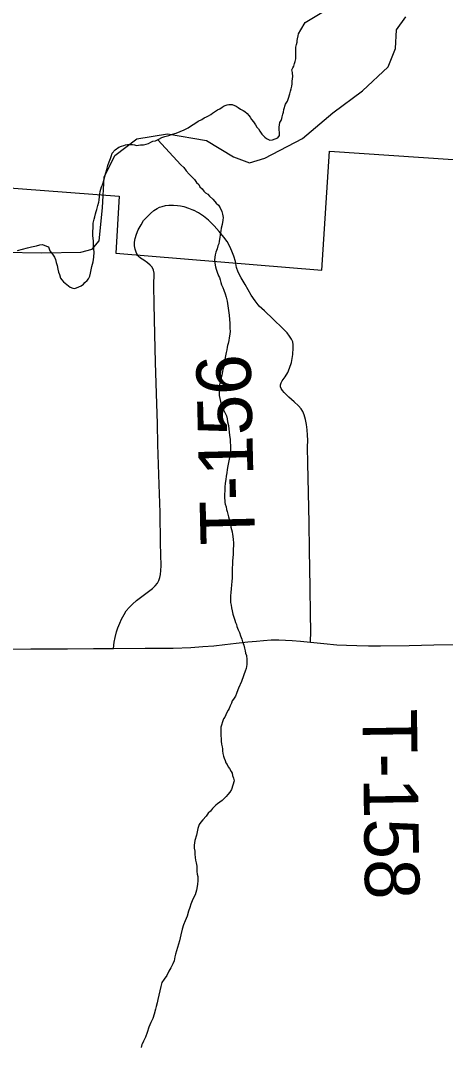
# Model space of a CAD drawing. Extents: x -11.4 to 84.1, y 11.1 to 59.
# Drawn here: x 29.384 to 29.827, y 45.561 to 46.631 of the extents above; entities that cross this region are included whole.
import ezdxf

# ---------------------------------------------------------------- set-up
doc = ezdxf.new("R2010")
doc.units = 0
for name, color, linetype in [('GM_X_Corporation', 7, 'Continuous'), ('GM_X_County_Road', 7, 'Continuous'), ('GM_X_Major_River', 7, 'Continuous'), ('GM_X_Minor_River', 7, 'Continuous'), ('GM_X_Rail_Line', 7, 'Continuous'), ('GM_X_Township_Road', 7, 'Continuous'), ('GM_X_Township_Road_Text', 7, 'Continuous')]:
    doc.layers.add(name, color=color, linetype=linetype)

msp = doc.modelspace()

# ---------------------------------------------------------------- linework, layer by layer
at = {"layer": 'GM_X_Corporation'}
msp.add_lwpolyline([(29.2807, 46.4633), (29.4869, 46.4478), (29.4834, 46.3883), (29.6985, 46.3706), (29.7063, 46.4947), (29.8352, 46.4859), (29.9622, 46.4788), (29.9464, 46.816), (29.9432, 46.8688), (29.9372, 46.8931), (29.8985, 46.896), (29.9001, 46.9199), (29.5467, 46.9424), (29.5434, 46.8903), (29.5061, 46.8927), (29.5056, 46.8842), (29.4682, 46.8866), (29.4704, 46.9206), (29.4238, 46.9236), (29.4228, 46.908), (29.2952, 46.9163)], dxfattribs=at)
at = {"layer": 'GM_X_County_Road'}
msp.add_lwpolyline([(29.345, 45.9758), (29.3948, 45.9761), (29.433, 45.9762), (29.4602, 45.9764), (29.4812, 45.9765), (29.5143, 45.9768), (29.5433, 45.977), (29.5619, 45.9777), (29.5743, 45.9785), (29.5859, 45.9794), (29.5972, 45.9807), (29.6091, 45.9821), (29.6211, 45.9835), (29.6303, 45.9843), (29.6377, 45.985), (29.6455, 45.9854), (29.6534, 45.9855), (29.6605, 45.9852), (29.6675, 45.9848), (29.676, 45.9841), (29.6866, 45.9831), (29.7003, 45.9817), (29.714, 45.9805), (29.7242, 45.9799), (29.7348, 45.9795), (29.747, 45.9793), (29.7594, 45.9794), (29.7894, 45.9798), (29.8151, 45.9802), (29.8386, 45.9808)], dxfattribs=at)
at = {"layer": 'GM_X_Major_River'}
for points in [[(29.6811, 46.6285), (29.702, 46.641)], [(29.6664, 46.5595), (29.6671, 46.5621), (29.6675, 46.5648), (29.6674, 46.5671), (29.6678, 46.5701), (29.6681, 46.572), (29.6677, 46.5766), (29.6672, 46.5792), (29.6683, 46.5812), (29.6691, 46.5831), (29.6698, 46.5858), (29.6705, 46.588), (29.6712, 46.5907), (29.6711, 46.5964), (29.6714, 46.5995), (29.6714, 46.6029), (29.6721, 46.6056), (29.6728, 46.6079), (29.6728, 46.6098), (29.6731, 46.6117), (29.6738, 46.6147), (29.6742, 46.6166), (29.6765, 46.621), (29.6811, 46.6285)], [(29.4617, 46.426), (29.4624, 46.4291), (29.4631, 46.4318), (29.4638, 46.4337), (29.4649, 46.4379), (29.466, 46.4413), (29.4663, 46.4436), (29.4666, 46.4474), (29.467, 46.4497), (29.4673, 46.4524), (29.468, 46.455), (29.4687, 46.4573), (29.4695, 46.4596), (29.4702, 46.4615), (29.4709, 46.4642), (29.4731, 46.4719), (29.4741, 46.4753), (29.4752, 46.4795), (29.4767, 46.4833), (29.4781, 46.4868), (29.4788, 46.4891), (29.4799, 46.4925), (29.4829, 46.496), (29.4867, 46.4987), (29.4893, 46.4999), (29.4919, 46.5003), (29.4938, 46.5011), (29.4957, 46.5015), (29.4991, 46.5016), (29.501, 46.5016), (29.5029, 46.5012), (29.5052, 46.5005), (29.5094, 46.501), (29.5124, 46.501), (29.5151, 46.5018), (29.5177, 46.5026), (29.52, 46.5038), (29.5223, 46.505), (29.5249, 46.5054), (29.5283, 46.507), (29.5317, 46.5086), (29.5347, 46.5098), (29.5389, 46.511), (29.5426, 46.5122), (29.5464, 46.5134), (29.5506, 46.515), (29.5547, 46.5169), (29.5589, 46.5189), (29.5626, 46.5212), (29.566, 46.5232), (29.5694, 46.5259), (29.5731, 46.5275), (29.5758, 46.5291), (29.578, 46.5302), (29.5803, 46.5314), (29.5826, 46.5326), (29.5844, 46.5342), (29.5897, 46.5377), (29.5919, 46.5388), (29.5946, 46.5404), (29.5965, 46.5416), (29.5995, 46.5428), (29.6014, 46.5432), (29.6048, 46.5432), (29.609, 46.5414), (29.6113, 46.5399), (29.6136, 46.5384), (29.6163, 46.537), (29.6182, 46.5358), (29.6205, 46.5336), (29.6221, 46.5317), (29.6236, 46.5299), (29.6252, 46.5276), (29.6271, 46.525), (29.6291, 46.522), (29.6306, 46.5197), (29.6322, 46.5178), (29.6337, 46.5152), (29.6357, 46.5122), (29.6388, 46.5092), (29.6407, 46.5077), (29.6442, 46.5059), (29.6468, 46.5063), (29.6525, 46.5083), (29.6543, 46.511), (29.6543, 46.514), (29.6538, 46.5167), (29.6538, 46.5197), (29.6545, 46.5243), (29.656, 46.5266), (29.6567, 46.5285), (29.657, 46.5304), (29.6577, 46.5331), (29.6585, 46.535), (29.6588, 46.538), (29.6606, 46.5434), (29.6625, 46.5465), (29.6635, 46.5499), (29.665, 46.5541), (29.6657, 46.5572), (29.6664, 46.5595)], [(29.381, 46.3912), (29.3863, 46.3925), (29.3916, 46.3937), (29.3957, 46.3949), (29.401, 46.3961), (29.4044, 46.397), (29.4071, 46.3974), (29.4113, 46.3955), (29.4132, 46.3948), (29.4148, 46.3907), (29.4175, 46.3873), (29.4195, 46.3843), (29.4206, 46.3816), (29.4214, 46.3786), (29.4223, 46.3756), (29.4231, 46.3718), (29.4239, 46.3684), (29.4247, 46.3661), (29.4259, 46.3623), (29.4274, 46.3605), (29.429, 46.3586), (29.4359, 46.353), (29.4386, 46.3519), (29.4409, 46.3515), (29.445, 46.3531), (29.4473, 46.3543), (29.4499, 46.3559), (29.4514, 46.3578), (29.4537, 46.3597), (29.4552, 46.3617), (29.4566, 46.3644), (29.4573, 46.3674), (29.458, 46.3708), (29.4587, 46.3743), (29.4598, 46.3792), (29.4605, 46.3842), (29.4608, 46.3895), (29.4603, 46.3956), (29.4602, 46.4013), (29.4597, 46.4062), (29.4596, 46.4108), (29.46, 46.4146), (29.4599, 46.4176), (29.4599, 46.4195), (29.4609, 46.4237), (29.4617, 46.426)]]:
    msp.add_lwpolyline(points, dxfattribs=at)
at = {"layer": 'GM_X_Minor_River'}
for points in [[(29.5273, 46.5065), (29.5515, 46.4804), (29.5546, 46.4774), (29.557, 46.474), (29.56, 46.4706), (29.5631, 46.4676), (29.5655, 46.465), (29.5678, 46.462), (29.5701, 46.4598), (29.5713, 46.4575), (29.5736, 46.4553), (29.5755, 46.453), (29.5771, 46.4511), (29.5794, 46.4496), (29.5813, 46.4478), (29.5848, 46.4444), (29.5867, 46.4422), (29.5883, 46.4403), (29.5906, 46.4384), (29.5925, 46.4354), (29.5941, 46.4316), (29.5949, 46.429), (29.5954, 46.4256), (29.595, 46.4225), (29.5943, 46.4183), (29.5933, 46.4145), (29.5929, 46.4115), (29.5926, 46.4096), (29.5923, 46.4069), (29.5919, 46.405), (29.5916, 46.4027), (29.5912, 46.4008), (29.5909, 46.3981), (29.5898, 46.3958), (29.5891, 46.3928), (29.588, 46.3893), (29.5873, 46.3867), (29.5866, 46.3813), (29.5867, 46.3779), (29.5875, 46.3741), (29.5883, 46.3715), (29.5891, 46.3684), (29.5907, 46.3647), (29.5915, 46.3628), (29.5923, 46.3605), (29.5931, 46.3579), (29.5939, 46.3552), (29.5951, 46.3526), (29.5963, 46.3499), (29.5975, 46.3461), (29.5987, 46.3424), (29.5995, 46.3382), (29.6003, 46.3336), (29.6012, 46.3287), (29.6016, 46.3238), (29.6021, 46.3192), (29.6025, 46.3154), (29.6026, 46.3124), (29.6026, 46.3097), (29.6027, 46.3071), (29.6023, 46.304), (29.6016, 46.3002), (29.6013, 46.2975), (29.6006, 46.2941), (29.5999, 46.2922), (29.5995, 46.2903), (29.5992, 46.2876), (29.5985, 46.2849), (29.5978, 46.2815), (29.5971, 46.2777), (29.5964, 46.2742), (29.5961, 46.2704), (29.595, 46.267), (29.5943, 46.2628), (29.5936, 46.2598), (29.5929, 46.2575), (29.5925, 46.2544), (29.5918, 46.251), (29.5919, 46.2479), (29.5912, 46.2453), (29.5912, 46.2426), (29.5913, 46.2399), (29.5933, 46.2308), (29.5941, 46.2278), (29.5957, 46.2252), (29.5969, 46.2229), (29.598, 46.221), (29.5988, 46.2188), (29.5996, 46.2157), (29.6001, 46.2127), (29.6009, 46.2089), (29.6013, 46.2051), (29.6018, 46.2021), (29.6022, 46.1983), (29.6027, 46.1945), (29.6027, 46.1911), (29.6031, 46.1884), (29.6032, 46.1854), (29.6032, 46.1827), (29.6033, 46.1797), (29.6026, 46.177)], [(29.6026, 46.177), (29.6019, 46.1739), (29.6012, 46.1701), (29.6005, 46.1667), (29.5998, 46.1629), (29.5994, 46.1595), (29.5987, 46.156), (29.5984, 46.1526), (29.5977, 46.1488), (29.5974, 46.1446), (29.5971, 46.1404), (29.5968, 46.1377), (29.5968, 46.1355), (29.5969, 46.1328), (29.5973, 46.1309), (29.5973, 46.1286), (29.5977, 46.1267), (29.5985, 46.1241), (29.5989, 46.1214), (29.5997, 46.1192), (29.6002, 46.1165), (29.601, 46.1135), (29.6022, 46.1097), (29.603, 46.1063), (29.6034, 46.1029), (29.6042, 46.1006), (29.6047, 46.0979), (29.6051, 46.0953), (29.6055, 46.0934), (29.6059, 46.0896), (29.6064, 46.0869), (29.6058, 46.077), (29.6058, 46.0744), (29.6055, 46.0713), (29.6052, 46.0675), (29.6052, 46.0641), (29.6049, 46.0607), (29.605, 46.0569), (29.605, 46.0535), (29.6047, 46.05), (29.6044, 46.0462), (29.6041, 46.0428), (29.6038, 46.0386), (29.6034, 46.0348), (29.6031, 46.0314), (29.6032, 46.0283), (29.6032, 46.0245), (29.6037, 46.0215), (29.6041, 46.0188), (29.6049, 46.0158), (29.6057, 46.0124), (29.6065, 46.009), (29.6077, 46.006), (29.6085, 46.0037), (29.6093, 46.0014), (29.6097, 45.9995), (29.6113, 45.9958), (29.6125, 45.9931), (29.6137, 45.9897), (29.6149, 45.9863), (29.6157, 45.9833), (29.6169, 45.9799), (29.6177, 45.9769), (29.6185, 45.9742), (29.6189, 45.9716), (29.6197, 45.9693), (29.6202, 45.9651), (29.6202, 45.9617), (29.6203, 45.9598), (29.6196, 45.9556), (29.6185, 45.9529), (29.617, 45.9491), (29.6159, 45.946), (29.6152, 45.9441), (29.6145, 45.9422), (29.6116, 45.9353), (29.6108, 45.9334), (29.6094, 45.9296), (29.6083, 45.9269), (29.6064, 45.9238), (29.6049, 45.9219), (29.6042, 45.9196), (29.6028, 45.9169), (29.6017, 45.9142), (29.6006, 45.9123), (29.5991, 45.9092), (29.5984, 45.9073), (29.5973, 45.905), (29.5958, 45.9031), (29.5947, 45.9), (29.5936, 45.8966), (29.5929, 45.8947), (29.5929, 45.8928), (29.5929, 45.8901), (29.593, 45.8878), (29.593, 45.8856), (29.5934, 45.8829), (29.5935, 45.8799), (29.5939, 45.8768), (29.5944, 45.8742), (29.5948, 45.8719)], [(29.5948, 45.8719), (29.5948, 45.87), (29.5952, 45.867), (29.596, 45.8643), (29.5965, 45.8624), (29.5976, 45.8598), (29.5984, 45.8575), (29.5996, 45.8556), (29.6008, 45.8534), (29.602, 45.8515), (29.6039, 45.8485), (29.6047, 45.8466), (29.6051, 45.8443), (29.6063, 45.8413), (29.6071, 45.8386), (29.6042, 45.8295), (29.6024, 45.8268), (29.6005, 45.8245), (29.5986, 45.8225), (29.5964, 45.8202), (29.5945, 45.8183), (29.5919, 45.8163), (29.5897, 45.8148), (29.5878, 45.8132), (29.5844, 45.8098), (29.5822, 45.8071), (29.5799, 45.8051), (29.5777, 45.802), (29.5744, 45.7982), (29.5721, 45.7955), (29.5703, 45.7932), (29.5692, 45.789), (29.5678, 45.7821), (29.566, 45.7764), (29.5653, 45.7718), (29.5654, 45.7684), (29.5658, 45.7653), (29.5658, 45.7623), (29.5663, 45.7589), (29.5667, 45.7562), (29.5675, 45.7532), (29.568, 45.7498), (29.568, 45.7471), (29.5681, 45.7441), (29.5685, 45.7414), (29.5689, 45.7391), (29.5689, 45.7365), (29.569, 45.7346), (29.5686, 45.7312), (29.5683, 45.7285), (29.5676, 45.7247), (29.5662, 45.7201), (29.5647, 45.717), (29.5632, 45.7136), (29.5618, 45.7101), (29.5607, 45.7067), (29.5592, 45.7029), (29.5578, 45.6979), (29.556, 45.6929), (29.5542, 45.6887), (29.5527, 45.6841), (29.5513, 45.6784), (29.5499, 45.6719), (29.5459, 45.6582), (29.5452, 45.6555), (29.5449, 45.6532), (29.5445, 45.6513), (29.5431, 45.6482), (29.5409, 45.644), (29.539, 45.6405), (29.5368, 45.636), (29.5338, 45.6321), (29.5316, 45.6286), (29.5306, 45.6244), (29.5295, 45.6199), (29.5284, 45.6153), (29.5274, 45.6111), (29.5267, 45.6076), (29.5256, 45.6038), (29.5249, 45.6008), (29.5234, 45.5958), (29.522, 45.5912), (29.5202, 45.587), (29.518, 45.582), (29.5162, 45.5767), (29.5144, 45.5717), (29.5125, 45.5675), (29.5111, 45.5644), (29.5107, 45.564), (29.51, 45.561)]]:
    msp.add_lwpolyline(points, dxfattribs=at)
at = {"layer": 'GM_X_Rail_Line'}
msp.add_lwpolyline([(29.3248, 46.3901), (29.4065, 46.3888), (29.447, 46.3895), (29.4589, 46.3926), (29.4663, 46.4013), (29.4695, 46.4356), (29.4713, 46.4675), (29.4826, 46.4899), (29.5056, 46.5074), (29.5376, 46.5126), (29.578, 46.5055), (29.6061, 46.4887), (29.6229, 46.4824), (29.6391, 46.4874), (29.6783, 46.5079), (29.7099, 46.5343), (29.7408, 46.5573), (29.7676, 46.5823), (29.7751, 46.6016), (29.7763, 46.6209), (29.7859, 46.6345)], dxfattribs=at)
at = {"layer": 'GM_X_Township_Road'}
for points in [[(29.4812, 45.9765), (29.4819, 45.983), (29.4828, 45.9881), (29.4844, 45.9938), (29.4858, 45.998), (29.4876, 46.0029), (29.4895, 46.007), (29.4921, 46.0119), (29.4945, 46.0156), (29.4974, 46.0193), (29.5008, 46.0227), (29.5052, 46.0266), (29.5219, 46.039), (29.5247, 46.0417), (29.5269, 46.0447), (29.5283, 46.0474), (29.5293, 46.0505), (29.53, 46.0536), (29.5306, 46.0577), (29.5307, 46.0626), (29.5303, 46.0863), (29.5297, 46.1183), (29.5287, 46.1472), (29.5281, 46.1683), (29.5273, 46.189), (29.5269, 46.2104), (29.526, 46.2423), (29.525, 46.2743), (29.5243, 46.304), (29.5235, 46.3351), (29.5232, 46.3546), (29.5234, 46.3675), (29.523, 46.3706), (29.5215, 46.3736), (29.5193, 46.3758), (29.5165, 46.3782), (29.5128, 46.3809), (29.5092, 46.3832), (29.507, 46.3853), (29.5051, 46.3883), (29.5036, 46.3924), (29.503, 46.396), (29.5031, 46.3996), (29.5037, 46.4035), (29.505, 46.408), (29.507, 46.4125), (29.5099, 46.4179), (29.5125, 46.4223), (29.5158, 46.4257), (29.5197, 46.4296), (29.5231, 46.4327), (29.5265, 46.4348), (29.5292, 46.4361), (29.5318, 46.437), (29.5353, 46.4378), (29.539, 46.4384), (29.5436, 46.4384), (29.5477, 46.4381), (29.5511, 46.4377), (29.5545, 46.4369), (29.5593, 46.4353), (29.5645, 46.4332)], [(29.6866, 45.9831), (29.6868, 45.9945), (29.6867, 46.0123), (29.6862, 46.0402), (29.6859, 46.0598), (29.6856, 46.0788), (29.685, 46.1075), (29.6844, 46.1386), (29.6837, 46.1696), (29.6836, 46.1861), (29.6837, 46.1934), (29.6836, 46.1987), (29.6831, 46.2044), (29.6824, 46.21), (29.6814, 46.2151), (29.6799, 46.22), (29.6784, 46.2233), (29.6767, 46.2262), (29.6739, 46.2293), (29.6694, 46.2336), (29.6641, 46.2383), (29.6592, 46.2431), (29.6574, 46.2451), (29.656, 46.2472), (29.6553, 46.2492), (29.6553, 46.2512), (29.6559, 46.2533), (29.6569, 46.2554), (29.6601, 46.2595), (29.6628, 46.2641), (29.6648, 46.2685), (29.6669, 46.2743), (29.6675, 46.2785), (29.668, 46.2828), (29.6685, 46.2896), (29.6684, 46.2929), (29.668, 46.2959), (29.6667, 46.2987), (29.6648, 46.3019), (29.6622, 46.3053), (29.6578, 46.31), (29.6478, 46.3196), (29.6385, 46.3281), (29.6331, 46.3332), (29.6288, 46.3386), (29.6247, 46.3444), (29.6184, 46.3558), (29.6141, 46.3626), (29.6111, 46.3684), (29.6093, 46.3734), (29.6083, 46.3795), (29.6066, 46.3851), (29.6046, 46.3903), (29.6025, 46.3952), (29.5995, 46.4003), (29.5963, 46.4049), (29.5914, 46.4109), (29.5861, 46.4166), (29.5802, 46.4225), (29.575, 46.4268), (29.5698, 46.4303), (29.5645, 46.4332)]]:
    msp.add_lwpolyline(points, dxfattribs=at)

# ---------------------------------------------------------------- texts
at = {"layer": 'GM_X_Township_Road_Text'}
for s, rotation, p in [('T-156', 91.4043, (29.6288, 46.0851)), ('T-158', 270.8407, (29.7407, 45.9132))]:
    msp.add_text(s, height=0.05682, rotation=rotation, dxfattribs=at).set_placement(p)

doc.saveas('drawing.dxf')
